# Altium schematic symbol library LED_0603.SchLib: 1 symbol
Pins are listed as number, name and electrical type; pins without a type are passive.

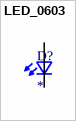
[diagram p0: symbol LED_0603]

## LED_0603
designator D?
Blue 470nm LED Indication - Discrete 3.3V 0603 _1608 Metric_; MP: LTST-S270TBKT; MF: Lite-On Inc.
footprint LED_0603
pins: 1 K1, 2 A2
